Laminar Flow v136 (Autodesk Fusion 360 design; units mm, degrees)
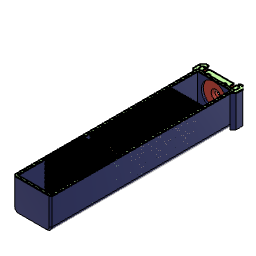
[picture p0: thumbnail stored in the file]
description: Part Number
part number: 73605T67_Brass Garden Hose Fitting
part number: 2706N24_Brass Garden Hose Fitting for Drinking Water
part number: 73605T49_Brass Garden Hose Fitting
named bodies: "Grid", "Backup", "7mm", "8mm", "Backup (1)", "Backup (1) (1)", "allowance", "Backup (1) (1) (1) (1)", "Chamber", "full", "full (1)", "v2-straightener", "inner-cone", "v2-straightener (1)", "grid-v2"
